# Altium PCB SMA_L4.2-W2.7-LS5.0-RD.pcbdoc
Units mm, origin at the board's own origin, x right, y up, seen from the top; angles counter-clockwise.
Board outline 18.7 x 15.52 mm, 2 copper layers (Top Layer, Bottom Layer), stack 0 mm thick; 1 components, 0 nets, 2 pads, 0 vias.
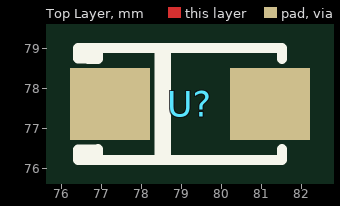
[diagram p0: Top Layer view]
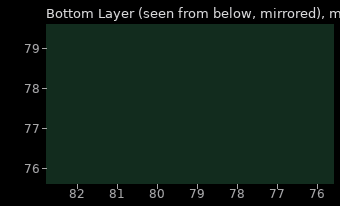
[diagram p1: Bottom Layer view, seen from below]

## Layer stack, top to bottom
Top Layer: signal copper (thickness not stored)
Bottom Layer: signal copper (thickness not stored)

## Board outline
88.55,69.85 69.85,69.85 69.85,85.368 88.55,85.368

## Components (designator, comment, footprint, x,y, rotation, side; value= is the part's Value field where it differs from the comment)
U? "" SMA_L4.2-W2.7-LS5.0-RD 79.2,77.618 r0 top

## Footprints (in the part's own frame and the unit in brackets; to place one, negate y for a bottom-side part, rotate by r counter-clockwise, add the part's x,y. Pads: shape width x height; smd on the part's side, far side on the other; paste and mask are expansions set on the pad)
SMA_L4.2-W2.7-LS5.0-RD [mm]
  rect 2x1.8 smd: 1(-2,0) 2(2,0)
  silkscreen extent -2.79,-1.4 2.3,1.4

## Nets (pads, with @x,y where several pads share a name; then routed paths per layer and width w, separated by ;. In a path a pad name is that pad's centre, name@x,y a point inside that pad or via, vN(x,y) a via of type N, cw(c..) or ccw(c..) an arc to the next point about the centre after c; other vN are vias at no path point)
pads on no net: U?.1 U?.2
